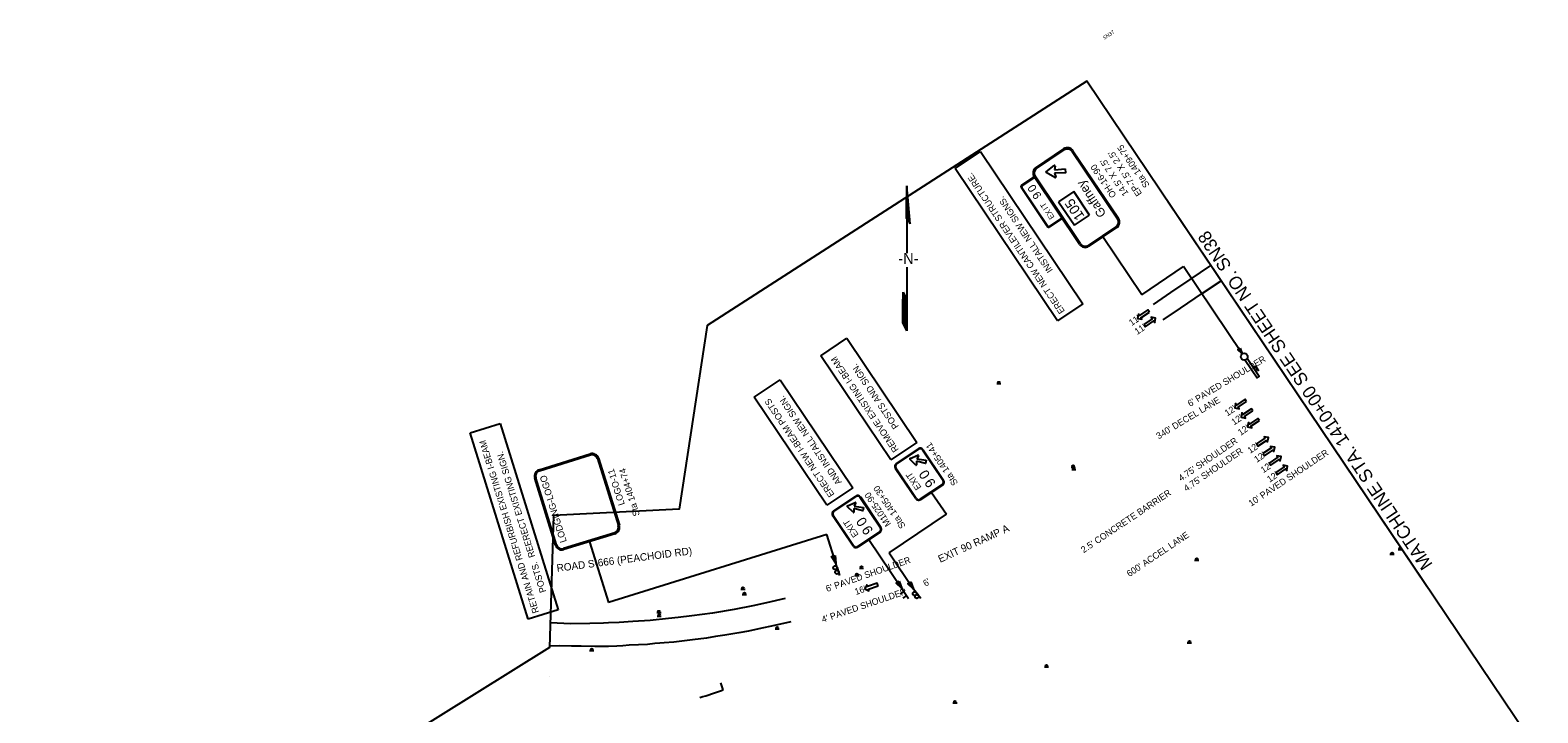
# Model space of a CAD drawing. Extents: x 1788362 to 1789997, y 1182358 to 1184055.
# Drawn here: x 1788374 to 1789997, y 1183321 to 1184055 of the extents above; entities that cross this region are included whole.
import ezdxf

# ---------------------------------------------------------------- set-up
doc = ezdxf.new("R2010")
doc.units = 0
for name, color, linetype in [('RD_EX_Road', 7, 'Continuous'), ('RD_HC_CL_Rel', 7, 'Continuous'), ('RD_HC_Data_Tic_Rel', 7, 'Continuous'), ('RD_PD_Final_LnLine', 7, 'Continuous'), ('RD_PD_Final_TX', 7, 'Continuous'), ('RD_SHT_MatchLine', 7, 'Continuous'), ('RD_SHT_ShtClip', 7, 'Continuous'), ('RD_SHT_TX', 7, 'Continuous'), ('RD_Sketch1', 7, 'Continuous'), ('RD_TX_RoadID', 7, 'Continuous'), ('SN_P_Signs', 7, 'Continuous')]:
    doc.layers.add(name, color=color, linetype=linetype)

# ---------------------------------------------------------------- blocks, each defined once
blk = doc.blocks.new('NA5')
at = {"layer": 'RD_Sketch1'}
for p, q in [((47.5, 65.9), (26.8, 37.4)), ((26.8, 30.6), (47.5, 65.9)), ((27.2, 37.5), (14.5, 19.8)), ((28.1, 38.3), (26.8, 30.6)), ((14.5, 19.8), (5.5, 7.2)), ((-3.5, -5.3), (-18.5, -26.3)), ((-18.5, -26.3), (-43.3, -60.9)), ((-30.6, -36.2), (-22.3, -24.7)), ((-22.3, -24.7), (-24, -34)), ((-41.6, -51.6), (-30.6, -36.2)), ((-43.3, -60.9), (-41.6, -51.6))]:
    blk.add_line(p, q, dxfattribs=at)
for points in [[(27.4, 37.8), (47.4, 65.8)], [(27.1, 37.6), (39.2, 54.5)], [(27.5, 34.9), (37.5, 48.8)], [(27.6, 37.9), (46.9, 64.9)], [(27.6, 35.5), (39, 51.5)], [(27.6, 35.3), (38.5, 50.6)], [(27.6, 35.1), (38, 49.7)], [(27.7, 36.2), (40.6, 54.2)], [(27.7, 36), (40.1, 53.3)], [(27.7, 35.8), (39.6, 52.4)], [(27.8, 38.1), (46.4, 64)], [(27.8, 36.8), (42.2, 56.8)], [(27.8, 36.6), (41.7, 56)], [(27.8, 36.4), (41.1, 55.1)], [(27.9, 37.4), (43.8, 59.5)], [(27.9, 37.2), (43.2, 58.6)], [(27.9, 37), (42.7, 57.7)], [(28, 38.1), (45.3, 62.2)], [(28, 37.9), (44.8, 61.3)], [(28, 37.7), (44.3, 60.4)], [(28.1, 38.3), (45.8, 63.1)], [(26.9, 37.5), (29.9, 41.7)], [(26.9, 31.3), (28.5, 33.6)], [(26.9, 31.1), (28, 32.7)], [(27, 32), (30.1, 36.3)], [(27, 31.8), (29.6, 35.4)], [(27, 31.5), (29.1, 34.5)], [(27.1, 32.6), (31.7, 39)], [(27.1, 32.4), (31.2, 38.1)], [(27.1, 32.2), (30.6, 37.2)], [(27.2, 33.2), (33.3, 41.6)], [(27.2, 33), (32.7, 40.7)], [(27.2, 32.8), (32.2, 39.9)], [(27.3, 33.9), (34.8, 44.3)], [(27.3, 33.7), (34.3, 43.4)], [(27.3, 33.4), (33.8, 42.5)], [(27.4, 34.5), (36.4, 47)], [(27.4, 34.3), (35.9, 46.1)], [(27.4, 34.1), (35.4, 45.2)], [(27.5, 34.7), (36.9, 47.9)], [(26.8, 30.7), (27, 30.9)], [(26.9, 30.9), (27.5, 31.8)], [(-43, -59), (-23.7, -32.1)], [(-43, -59.2), (-23.7, -32.3)], [(-42.9, -58.6), (-23.6, -31.7)], [(-42.9, -58.8), (-23.7, -31.9)], [(-42.8, -58.1), (-23.5, -31.2)], [(-42.8, -58.3), (-23.6, -31.4)], [(-42.7, -57.5), (-23.4, -30.6)], [(-42.7, -57.7), (-23.5, -30.8)], [(-42.7, -57.9), (-23.5, -31)], [(-42.6, -57), (-23.3, -30.1)], [(-42.6, -57.2), (-23.4, -30.4)], [(-42.5, -56.4), (-23.2, -29.5)], [(-42.5, -56.6), (-23.2, -29.7)], [(-42.5, -56.8), (-23.3, -29.9)], [(-42.4, -55.9), (-23.1, -29)], [(-42.4, -56.1), (-23.2, -29.3)], [(-42.3, -55.3), (-23, -28.4)], [(-42.3, -55.5), (-23, -28.6)], [(-42.3, -55.7), (-23.1, -28.8)], [(-42.2, -54.8), (-22.9, -27.9)], [(-42.2, -55), (-23, -28.2)], [(-42.1, -54.4), (-22.8, -27.5)], [(-42.1, -54.6), (-22.9, -27.7)], [(-42, -53.7), (-22.7, -26.8)], [(-42, -53.9), (-22.7, -27.1)], [(-42, -54.2), (-22.8, -27.3)], [(-41.9, -53.3), (-22.6, -26.4)], [(-41.9, -53.5), (-22.7, -26.6)], [(-41.8, -52.6), (-22.5, -25.7)], [(-41.8, -52.8), (-22.5, -26)], [(-41.8, -53.1), (-22.6, -26.2)], [(-41.7, -52.2), (-22.4, -25.3)], [(-41.7, -52.4), (-22.5, -25.5)], [(-41.6, -51.7), (-22.3, -24.9)], [(-41.6, -52), (-22.4, -25.1)], [(-43.3, -60.8), (-24, -33.9)], [(-43.2, -60.1), (-23.9, -33.2)], [(-43.2, -60.3), (-23.9, -33.4)], [(-43.2, -60.5), (-24, -33.6)], [(-43.1, -59.7), (-23.8, -32.8)], [(-43.1, -59.9), (-23.9, -33)], [(-43, -59.4), (-23.8, -32.5)]]:
    blk.add_lwpolyline(points, dxfattribs=at)
blk.add_text('-N-', height=11.81, rotation=324.3865, dxfattribs=at).set_placement((-8.8, 3))
blk = doc.blocks.new('SARRW2')
at = {"layer": 'RD_PD_Final_LnLine'}
blk.add_lwpolyline([(-12, 1.2), (-12, -1.2), (-2.8, -1.2), (-2.8, -2.8), (0, 0), (-2.8, 2.8), (-2.8, 1.2)], close=True, dxfattribs=at)

msp = doc.modelspace()

# ---------------------------------------------------------------- linework, layer by layer
at = {"layer": 'RD_EX_Road'}
for points in [[(1789644.3, 1183802.4), (1789621.9, 1183787.2), (1789601.1, 1183773.1), (1789582.3, 1183760.3)], [(1789593.3, 1183743.9), (1789611.8, 1183756.4), (1789635.7, 1183772.5), (1789655.6, 1183785.7)], [(1789186.4, 1183443.8), (1789166.2, 1183439.3), (1789151.4, 1183436.1), (1789131.3, 1183432.1), (1789108.2, 1183428.1), (1789086, 1183425.2), (1789071.2, 1183423.3), (1789060.8, 1183422.3), (1789041, 1183420), (1789022.3, 1183419), (1789007.6, 1183418.2), (1788996.2, 1183417.6), (1788990.7, 1183417.2), (1788975.9, 1183416.8), (1788955.6, 1183416.7), (1788933.5, 1183417.7)], [(1789192.5, 1183418.6), (1789171.5, 1183414), (1789161.3, 1183411.8), (1789146.7, 1183408.7), (1789136.5, 1183406.8), (1789121.5, 1183404.3), (1789111.5, 1183402.8), (1789101.5, 1183401.3), (1789086.5, 1183399.4), (1789077.9, 1183398.4), (1789066.4, 1183397), (1789056, 1183396.3), (1789051.5, 1183395.7), (1789046.2, 1183395.3), (1789038.3, 1183394.5), (1789028.6, 1183394), (1789018.5, 1183393.6), (1789011.5, 1183393), (1789005, 1183392.7), (1788996.3, 1183392.1), (1788981.5, 1183392.3), (1788966.6, 1183392.5), (1788956.2, 1183392.7), (1788943.7, 1183392.8), (1788933.3, 1183392.7)]]:
    msp.add_lwpolyline(points, dxfattribs=at)
at = {"layer": 'RD_HC_CL_Rel'}
msp.add_arc((1788808, 1184258.7), 965, 287.2774, 288.8471, dxfattribs=at)
at = {"layer": 'RD_HC_Data_Tic_Rel'}
msp.add_line((1789119.7, 1183345.4), (1789117.1, 1183353), dxfattribs=at)
at = {"layer": 'RD_PD_Final_LnLine'}
msp.add_line((1788933.1, 1183359.6), (1788933.1, 1183359.6), dxfattribs=at)
at = {"layer": 'RD_SHT_MatchLine'}
msp.add_lwpolyline([(1789877.1, 1183456.7), (1789737.5, 1183664.1), (1789597.8, 1183871.4)], dxfattribs=at)
at = {"layer": 'RD_SHT_ShtClip'}
msp.add_lwpolyline([(1789873, 1183462.7), (1789616.4, 1183843.9), (1789510.9, 1184000.6), (1789102.3, 1183737.7), (1789072.3, 1183540), (1788937.1, 1183533.1), (1788932.8, 1183391.2), (1788373.6, 1183042.3), (1788602.9, 1182624.6), (1788749.4, 1182357.6), (1789114.8, 1182592.7), (1789124.7, 1182718.7), (1789996.5, 1183279.6)], close=True, dxfattribs=at)
at = {"layer": 'SN_P_Signs'}
for p, q in [((1789369.2, 1183906.5), (1789396.4, 1183924.8)), ((1789396.4, 1183924.8), (1789506.7, 1183761)), ((1789479.5, 1183742.7), (1789369.2, 1183906.5)), ((1789496.9, 1183881.8), (1789480.6, 1183870.8)), ((1789514, 1183856.5), (1789496.9, 1183881.8)), ((1789480.6, 1183870.8), (1789497.6, 1183845.5)), ((1789497.6, 1183845.5), (1789514, 1183856.5)), ((1789570.1, 1183770.6), (1789528.1, 1183833)), ((1789570.1, 1183770.6), (1789615.2, 1183801)), ((1789678.3, 1183707.1), (1789615.2, 1183801)), ((1789506.7, 1183761), (1789479.5, 1183742.7)), ((1789224.7, 1183705.1), (1789252.6, 1183723.9)), ((1789252.6, 1183723.9), (1789328, 1183611.9)), ((1789300.1, 1183593.1), (1789224.7, 1183705.1)), ((1789691, 1183691.3), (1789693.2, 1183692.8)), ((1789692.1, 1183694.6), (1789695.9, 1183688.8)), ((1789692.4, 1183689.1), (1789694.8, 1183690.6)), ((1789153, 1183660.5), (1789180.9, 1183679.3)), ((1789180.9, 1183679.3), (1789259.1, 1183563.1)), ((1789414.1, 1183675.2), (1789418.6, 1183675.2)), ((1789231.2, 1183544.3), (1789153, 1183660.5)), ((1788847.4, 1183622.2), (1788879.5, 1183632.2)), ((1788909.8, 1183421.7), (1788847.4, 1183622.2)), ((1788879.5, 1183632.2), (1788941.9, 1183431.7)), ((1789328, 1183611.9), (1789300.1, 1183593.1)), ((1789305.9, 1183588.9), (1789329.8, 1183605)), ((1789306.2, 1183588.4), (1789330.1, 1183604.5)), ((1789334.3, 1183603.7), (1789356.4, 1183570.8)), ((1789334.8, 1183604), (1789356.9, 1183571.2)), ((1789327, 1183551.1), (1789304.9, 1183583.9)), ((1789327.5, 1183551.4), (1789305.4, 1183584.2)), ((1789494, 1183585.2), (1789498.5, 1183585.2)), ((1789494.8, 1183582.7), (1789499.3, 1183582.7)), ((1789259.1, 1183563.1), (1789231.2, 1183544.3)), ((1789355.6, 1183566.7), (1789331.7, 1183550.6)), ((1789355.9, 1183566.2), (1789332, 1183550.1)), ((1789344, 1183558.1), (1789359.8, 1183534.5)), ((1789238.4, 1183538), (1789262.3, 1183554.1)), ((1789238.7, 1183537.5), (1789262.6, 1183553.6)), ((1789266.8, 1183552.8), (1789288.9, 1183519.9)), ((1789267.3, 1183553.1), (1789289.4, 1183520.3)), ((1789259.5, 1183500.2), (1789237.4, 1183533)), ((1789260, 1183500.5), (1789237.9, 1183533.3)), ((1789298.2, 1183493), (1789359.8, 1183534.5)), ((1789231.1, 1183512.7), (1788996, 1183439.6)), ((1789240.7, 1183481.9), (1789231.1, 1183512.7)), ((1789288.1, 1183515.8), (1789264.2, 1183499.7)), ((1789288.4, 1183515.3), (1789264.5, 1183499.2)), ((1789276.5, 1183507.2), (1789311.9, 1183454.5)), ((1788975.7, 1183505), (1788996, 1183439.6)), ((1789298.2, 1183493), (1789324.5, 1183453.9)), ((1789837.3, 1183491.4), (1789841.8, 1183491.4)), ((1789846, 1183496.5), (1789850.5, 1183496.5)), ((1789243.4, 1183473.3), (1789240.7, 1183481.9)), ((1789245.3, 1183468.5), (1789242.7, 1183477.1)), ((1789266.2, 1183476.6), (1789270.7, 1183476.6)), ((1789627.1, 1183485.1), (1789631.6, 1183485.1)), ((1789261.3, 1183468.6), (1789265.8, 1183468.6)), ((1789138.6, 1183454), (1789143.1, 1183454)), ((1789140.1, 1183448.2), (1789144.6, 1183448.2)), ((1789314.1, 1183451.3), (1789310, 1183448.5)), ((1789311.9, 1183454.5), (1789319.2, 1183443.7)), ((1789316.9, 1183447.1), (1789312.8, 1183444.3)), ((1789330.1, 1183446.8), (1789324.5, 1183453.9)), ((1789332.5, 1183443.8), (1789326.9, 1183450.8)), ((1788941.9, 1183431.7), (1788909.8, 1183421.7)), ((1789048.2, 1183428.7), (1789052.7, 1183428.7)), ((1789048.5, 1183424.9), (1789053, 1183424.9)), ((1789175.5, 1183411.2), (1789180, 1183411.2)), ((1789619.2, 1183396.2), (1789623.7, 1183396.2)), ((1788975.8, 1183388), (1788980.3, 1183388)), ((1789465.3, 1183370.3), (1789469.8, 1183370.3)), ((1789366.9, 1183331.7), (1789371.4, 1183331.7))]:
    msp.add_line(p, q, dxfattribs=at)
for points in [[(1789456.3, 1183907.5), (1789486.1, 1183927.6)], [(1789456.9, 1183906.5), (1789486.8, 1183926.6)], [(1789495.1, 1183925), (1789544, 1183852.4)], [(1789496.1, 1183925.7), (1789545, 1183853)], [(1789440.9, 1183888.5), (1789454.3, 1183897.5), (1789454.6, 1183897)], [(1789454.6, 1183897), (1789441.2, 1183888)], [(1789503.2, 1183824.9), (1789454.3, 1183897.5)], [(1789504.2, 1183825.5), (1789455.3, 1183898.2)], [(1789467.3, 1183903.2), (1789475.8, 1183909.9)], [(1789476.7, 1183896.8), (1789467.3, 1183902.2)], [(1789476.8, 1183909.3), (1789476.1, 1183905)], [(1789476.1, 1183905), (1789487.8, 1183906.3)], [(1789487.8, 1183906.3), (1789488.1, 1183902.1), (1789476.3, 1183901.7)], [(1789476.3, 1183901.7), (1789477.6, 1183897.5)], [(1789468.5, 1183844.2), (1789440.4, 1183886)], [(1789440.9, 1183886.3), (1789469, 1183844.5)], [(1789470.7, 1183844.2), (1789484.1, 1183853.2), (1789484.5, 1183852.7), (1789471, 1183843.7)], [(1789542.4, 1183844), (1789512.5, 1183823.9)], [(1789543.1, 1183843), (1789513.2, 1183822.9)], [(1789681.4, 1183700.5), (1789694.3, 1183681.3), (1789696.6, 1183682.9), (1789683.6, 1183702.2)], [(1788921.4, 1183582.4), (1788976.4, 1183599.5)], [(1788921.8, 1183581.3), (1788976.8, 1183598.4)], [(1788984.3, 1183594.4), (1789006.8, 1183522.2)], [(1788985.5, 1183594.8), (1789007.9, 1183522.6)], [(1789327, 1183587.5), (1789320.6, 1183593.8)], [(1789320.8, 1183594.6), (1789329.1, 1183598.1)], [(1789338.1, 1183592.7), (1789337.4, 1183589.1), (1789327.6, 1183591.5)], [(1789327.6, 1183591.5), (1789327.8, 1183587.8)], [(1789329.7, 1183597.5), (1789328.1, 1183594.1)], [(1789328.1, 1183594.1), (1789338.1, 1183592.7)], [(1788939.2, 1183501.2), (1788916.7, 1183573.4)], [(1788940.3, 1183501.6), (1788917.9, 1183573.7)], [(1789259.5, 1183536.6), (1789253.1, 1183542.9)], [(1789253.3, 1183543.7), (1789261.6, 1183547.2)], [(1789270.6, 1183541.8), (1789269.9, 1183538.2), (1789260.1, 1183540.6)], [(1789260.1, 1183540.6), (1789260.3, 1183536.9)], [(1789262.2, 1183546.6), (1789260.6, 1183543.2)], [(1789260.6, 1183543.2), (1789270.6, 1183541.8)], [(1789002.8, 1183514.7), (1788947.8, 1183497.6)], [(1789003.2, 1183513.6), (1788948.2, 1183496.5)]]:
    msp.add_lwpolyline(points, dxfattribs=at)
for points in [[(1789676.2, 1183713.1), (1789678.3, 1183707.1), (1789673.6, 1183711.4)], [(1789240.3, 1183490.3), (1789240.7, 1183481.9), (1789236.3, 1183489.1)], [(1789309.1, 1183462.5), (1789311.9, 1183454.5), (1789305.7, 1183460.2)], [(1789321.6, 1183461.8), (1789324.5, 1183453.9), (1789318.2, 1183459.5)]]:
    msp.add_lwpolyline(points, close=True, dxfattribs=at)
for centre, radius in [((1789680.4, 1183704.1), 3.71), ((1789416.3, 1183676.2), 1), ((1789496.2, 1183586.2), 1), ((1789497.1, 1183583.8), 1), ((1789839.6, 1183492.4), 1), ((1789848.3, 1183497.5), 1), ((1789240.1, 1183477), 2), ((1789268.5, 1183477.6), 1), ((1789629.3, 1183486.1), 1), ((1789242.1, 1183472.2), 2), ((1789263.5, 1183469.6), 1), ((1789140.9, 1183455), 1), ((1789142.4, 1183449.2), 1), ((1789325.7, 1183449.1), 2), ((1789328.1, 1183446), 2), ((1789050.4, 1183429.7), 1), ((1789050.8, 1183425.9), 1), ((1789177.8, 1183412.3), 1), ((1789621.5, 1183397.2), 1), ((1788978.1, 1183389), 1), ((1789467.5, 1183371.3), 1), ((1789369.1, 1183332.7), 1)]:
    msp.add_circle(centre, radius, dxfattribs=at)
for centre, radius, start, end in [((1789490.1, 1183921.7), 7.2, 33.9476, 123.9476), ((1789490.1, 1183921.7), 6, 33.9476, 123.9476), ((1789460.3, 1183901.6), 7.2, 123.9476, 213.9476), ((1789460.3, 1183901.6), 6, 123.9476, 213.9476), ((1789467.6, 1183902.8), 0.6, 127.967, 239.9283), ((1789476.2, 1183909.4), 0.6, 350.5015, 127.967), ((1789477, 1183897.3), 0.6, 239.9283, 17.3937), ((1789441.9, 1183887), 1.8, 123.9476, 213.9476), ((1789441.9, 1183887), 1.2, 123.9476, 213.9476), ((1789539.1, 1183849), 6, 303.9476, 33.9476), ((1789539.1, 1183849), 7.2, 303.9476, 33.9476), ((1789470, 1183845.2), 1.8, 213.9476, 303.9476), ((1789470, 1183845.2), 1.2, 213.9476, 303.9476), ((1789509.2, 1183828.9), 7.2, 213.9476, 303.9476), ((1789509.2, 1183828.9), 6, 213.9476, 303.9476), ((1789331.8, 1183602), 3.6, 33.9476, 123.9476), ((1789331.8, 1183602), 3, 33.9476, 123.9476), ((1788978.6, 1183592.6), 7.2, 17.2774, 107.2774), ((1788978.6, 1183592.6), 6, 17.2774, 107.2774), ((1789307.9, 1183585.9), 3.6, 123.9476, 213.9476), ((1789307.9, 1183585.9), 3, 123.9476, 213.9476), ((1789320.9, 1183594.2), 0.45, 112.7697, 225.1255), ((1789329.3, 1183597.7), 0.45, 334.9855, 112.7697), ((1788923.6, 1183575.5), 7.2, 107.2774, 197.2774), ((1788923.6, 1183575.5), 6, 107.2774, 197.2774), ((1789327.3, 1183587.8), 0.45, 225.1255, 2.9097), ((1789353.9, 1183569.2), 3, 303.9476, 33.9476), ((1789353.9, 1183569.2), 3.6, 303.9476, 33.9476), ((1789253.4, 1183543.3), 0.45, 112.7697, 225.1255), ((1789261.8, 1183546.8), 0.45, 334.9855, 112.7697), ((1789264.3, 1183551.1), 3.6, 33.9476, 123.9476), ((1789264.3, 1183551.1), 3, 33.9476, 123.9476), ((1789330, 1183553.1), 3.6, 213.9476, 303.9476), ((1789330, 1183553.1), 3, 213.9476, 303.9476), ((1789240.4, 1183535), 3.6, 123.9476, 213.9476), ((1789240.4, 1183535), 3, 123.9476, 213.9476), ((1789259.8, 1183536.9), 0.45, 225.1255, 2.9097), ((1789001, 1183520.4), 6, 287.2774, 17.2774), ((1789001, 1183520.4), 7.2, 287.2774, 17.2774), ((1789286.4, 1183518.3), 3, 303.9476, 33.9476), ((1789286.4, 1183518.3), 3.6, 303.9476, 33.9476), ((1788946, 1183503.3), 7.2, 197.2774, 287.2774), ((1788946, 1183503.3), 6, 197.2774, 287.2774), ((1789262.5, 1183502.2), 3.6, 213.9476, 303.9476), ((1789262.5, 1183502.2), 3, 213.9476, 303.9476)]:
    msp.add_arc(centre, radius, start, end, dxfattribs=at)

# ---------------------------------------------------------------- block references
at = {"layer": 'RD_PD_Final_LnLine', "xscale": 1.1999999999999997}
for p, yscale, rotation in [((1789565.6, 1183745.2), 1.2000000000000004, -146.05256015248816), ((1789585.1, 1183745.6), 1.2, 33.94743984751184), ((1789670.2, 1183649), 1.2000000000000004, -146.05256015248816), ((1789677, 1183638.9), 1.2000000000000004, -146.05256015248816), ((1789684, 1183628.5), 1.2000000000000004, -146.05256015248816), ((1789706.4, 1183617), 1.2, 33.94743984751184), ((1789713.4, 1183606.6), 1.2, 33.94743984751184), ((1789720.2, 1183596.5), 1.2, 33.94743984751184), ((1789727.1, 1183586.3), 1.2, 33.94743984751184), ((1789272.2, 1183454.3), 1.2000000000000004, -161.04660411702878)]:
    msp.add_blockref('SARRW2', p, dxfattribs=dict(at, yscale=yscale, rotation=rotation))
at = {"layer": 'RD_SHT_MatchLine', "rotation": 35.61349782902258}
msp.add_blockref('NA5', (1789316.9, 1183806.6), dxfattribs=at)

# ---------------------------------------------------------------- texts
at = {"layer": 'RD_PD_Final_TX'}
for s, rotation, p in [("11'", 33.9474, (1789559.2, 1183736.9)), ("11'", 33.9474, (1789565.3, 1183727.4)), ("6' PAVED SHOULDER", 31.1375, (1789622.2, 1183650)), ("340' DECEL LANE", 31.1375, (1789588.3, 1183615)), ("12'", 33.9474, (1789662.3, 1183639.7)), ("12'", 33.9474, (1789669.5, 1183630)), ("12'", 33.9474, (1789676.5, 1183618.8)), ("4.75' SHOULDER", 34.4573, (1789612.5, 1183569.7)), ("4.75' SHOULDER", 34.4573, (1789618.3, 1183558.7)), ("12'", 33.9474, (1789686.9, 1183599.5)), ("10' PAVED SHOULDER", 33.9474, (1789688, 1183542.6)), ("12'", 33.9474, (1789694, 1183589.8)), ("12'", 33.9474, (1789701, 1183578.5)), ("12'", 33.9474, (1789707.8, 1183568.4)), ("2.5' CONCRETE BARRIER", 33.7643, (1789507.6, 1183492.5)), ("600' ACCEL LANE", 33.9476, (1789556.9, 1183466.8)), ("6' PAVED SHOULDER", 19.324, (1789231.5, 1183450.8)), ("6'", 33.9474, (1789337.6, 1183456.4)), ("4' PAVED SHOULDER", 18.852, (1789226.9, 1183417.7)), ("16'", 18.9534, (1789262.5, 1183447.5))]:
    msp.add_text(s, height=7, rotation=rotation, dxfattribs=at).set_placement(p)
at = {"layer": 'RD_SHT_MatchLine'}
msp.add_text('MATCHLINE STA. 1410+00 SEE SHEET NO. SN38', height=14, rotation=123.9476, dxfattribs=at).set_placement((1789883.8, 1183480.6))
at = {"layer": 'RD_SHT_TX'}
msp.add_text('SN37', height=4, rotation=32.7534, dxfattribs=at).set_placement((1789529.7, 1184045))
at = {"layer": 'RD_TX_RoadID'}
for s, rotation, p in [('EXIT 90 RAMP A', 24.5815, (1789353.2, 1183482.2)), ('ROAD S-666 (PEACHOID RD)', 7.3914, (1788940.9, 1183472.5))]:
    msp.add_text(s, height=8, rotation=rotation, dxfattribs=at).set_placement(p)
at = {"layer": 'SN_P_Signs'}
for s, height, rotation, p in [('Sta 1409+75', 7, 123.9477, (1789578.9, 1183888.8)), ("14.5' X 7.5'", 7, 123.9477, (1789556.3, 1183879.8)), ("EP-7.5' X 2.5'", 7, 123.9477, (1789570.7, 1183879.7)), ('ERECT NEW CANTILEVER STRUCTURE.', 7, 123.9477, (1789487.6, 1183753.1)), ('OH-16-90', 7, 123.9477, (1789543.2, 1183877.9)), ('0', 9, 123.9476, (1789457.7, 1183885)), ('9', 9, 123.9476, (1789462.8, 1183877.4)), ('Gaffney', 9.6, 123.9476, (1789532.3, 1183857.9)), ('INSTALL NEW SIGNS.', 7, 123.9477, (1789474.8, 1183797.2)), ('T', 6, 123.9476, (1789468.2, 1183866.7)), ('I', 6, 123.9476, (1789469.8, 1183864.2)), ('105', 10.8, 123.9476, (1789508.9, 1183855.4)), ('X', 6, 123.9476, (1789473.7, 1183858.6)), ('E', 6, 123.9476, (1789476.5, 1183854.3)), ('REMOVE EXISTING I-BEAM', 7, 123.9477, (1789308.8, 1183604.1)), ('POSTS AND SIGN.', 7, 123.9477, (1789308.9, 1183629.1)), ('ERECT NEW I-BEAM POSTS', 7, 123.9477, (1789239.6, 1183555.8)), ('AND INSTALL NEW SIGN.', 7, 123.9477, (1789247.5, 1183569.1)), ('RETAIN AND REFURBISH EXISTING I-BEAM', 7, 107.2775, (1788921.4, 1183429.2)), ('Sta 1405+41', 7, 123.9477, (1789372.7, 1183568.2)), ('POSTS.  REERECT EXISTING SIGN.', 7, 107.2775, (1788929.2, 1183451.3)), ('LODGING-LOGO', 7.2, 107.2774, (1788951.3, 1183505.2)), ('LOGO-11', 7, 107.2775, (1789013.8, 1183545.2)), ('Sta 1404+74', 7, 107.2775, (1789029.9, 1183533.7)), ('EXIT', 7, 123.9476, (1789333.2, 1183563.4)), ('0', 10.8, 123.9476, (1789342.9, 1183576.9)), ('9', 10.8, 123.9476, (1789349, 1183567.9)), ('M1025-90', 7, 123.9477, (1789300.6, 1183524.1)), ('Sta 1405+30', 7, 123.9477, (1789316.3, 1183522)), ('EXIT', 7, 123.9476, (1789265.7, 1183512.5)), ('0', 10.8, 123.9476, (1789275.4, 1183526)), ('9', 10.8, 123.9476, (1789281.5, 1183517))]:
    msp.add_text(s, height=height, rotation=rotation, dxfattribs=at).set_placement(p)

doc.saveas('drawing.dxf')
